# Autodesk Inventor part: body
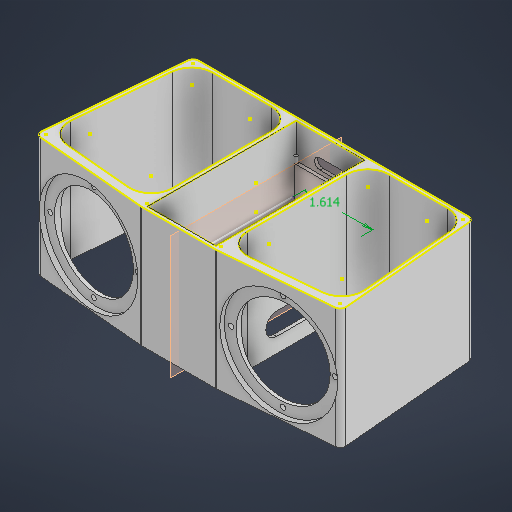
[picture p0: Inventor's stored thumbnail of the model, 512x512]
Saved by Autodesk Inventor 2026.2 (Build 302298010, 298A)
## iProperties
Created: 2026-08
Part Number: body
Material: Generic
Document SubType Name: Modeling
Designer: cpEwe
Density: 1 g/cm^3
Appearance: Default
Author: cpEwe
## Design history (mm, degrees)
sketch "Sketch1"
  geometry: L1 (-17.25, 41.25)-(17.25, 41.25); L2 (17.25, 41.25)-(17.25, -41.25); L3 (17.25, -41.25)-(-17.25, -41.25); L4 (-17.25, -41.25)-(-17.25, 41.25); L5 (-17.25, 41.25)-(17.25, -41.25); L6 (17.25, 41.25)-(-17.25, -41.25); C1 r 1 at (17.25, 41.25); C2 r 1 at (17.25, -41.25); C3 r 1 at (-17.25, -41.25); C4 r 1 at (-17.25, 41.25); 1 further point
  constraints: 12 end point, 4 centre point, 4 coincident, 3 equal radius, 2 midpoint, 2 parallel, 1 horizontal, 1 perpendicular
  dimensions: "d0" = 82.5 distance of L1.end L2.end; "d1" = 34.5 distance of L2.end L3.end; "d2" = 2 diameter of C1
extrude "Extrusion1" new body sketch "Sketch1" distance "d3" = 25; taper "d4" = 0 deg
sketch "Sketch2"
  geometry: L1 (0, 0)-(34.5, 0); L2 (34.5, 0)-(34.5, -82.5); L3 (34.5, -82.5)-(0, -82.5); L4 (36, -47.65)-(36, -82.65); L5 (36, -82.65)-(-1.5, -82.65); L6 (-1.5, -82.65)-(-1.5, -47.65); L7 (-1.5, -47.65)-(36, -47.65); L8 (36, -47.65)-(-1.5, -82.65); L9 (36, -82.65)-(-1.5, -47.65); L10 (0, -82.5)-(0, 0); C1 r 1 at (0, 0) reference; C2 r 1 at (34.5, -82.5) reference; C3 r 1 at (-1.5, -82.65); C4 r 1 at (-1.5, -47.65); C5 r 1 at (36, -47.65); C6 r 1 at (36, -82.65); 2 further points
  constraints: 20 end point, 4 centre point, 4 coincident, 3 equal radius, 3 parallel, 3 perpendicular, 2 midpoint, 1 horizontal
  dimensions: "d5" = 35 distance of L5.end L6.end; "d6" = 37.5 distance of L6.end L4.start; "d7" = 2 diameter of C3
extrude "Extrusion2" join sketch "Sketch2" distance "d8" = 7; taper "d9" = 0 deg
sketch "Sketch5"
  geometry: L1 (-3.25, 85.75)-(37.75, 85.75); L2 (37.75, 85.75)-(37.75, -3.25); L3 (37.75, -3.25)-(-3.25, -3.25); L4 (-3.25, -3.25)-(-3.25, 85.75); L5 (-3.25, 85.75)-(37.75, -3.25); L6 (37.75, 85.75)-(-3.25, -3.25); L7 (39.655, 87.655)-(-5.155, 87.655); L8 (-5.155, 87.655)-(-5.155, -5.155); L9 (-5.155, -5.155)-(39.655, -5.155); L10 (39.655, -5.155)-(39.655, 87.655); 1 further point
  constraints: 20 end point, 4 parallel, 2 midpoint, 2 perpendicular, 1 horizontal, 3 other
  dimensions: "d14" = 41 distance of L2.end L3.end; "d27" = 89 distance of L3.end L1.start; "d28" = 1.905 distance between parallel lines of L1 L7
extrude "Extrusion4" join sketch "Sketch5" stored distance "d16" = 2.54; taper "d17" = 0 deg
sketch "Sketch6"
  geometry: L1 (34.5, 0)-(0, 0); L2 (34.5, -1)-(0, -1); L3 (0, 1)-(34.5, 1); L4 (0, 82.5)-(34.5, 82.5); L5 (0, 83.5)-(34.5, 83.5); L6 (34.5, 81.5)-(0, 81.5); A1 r 1 centre (34.5, 0) between (34.5, -1) and (34.5, 1) reference; A2 r 1 centre (0, 0) between (0, -1) and (0, 1) reference; A3 r 1 centre (34.5, 0) between (34.5, -1) and (34.5, 1); A4 r 1 centre (0, 0) between (0, 1) and (0, -1); A5 r 1 centre (0, 82.5) between (0, 83.5) and (0, 81.5) reference; A6 r 1 centre (34.5, 82.5) between (34.5, 83.5) and (34.5, 81.5) reference; A7 r 1 centre (0, 82.5) between (0, 83.5) and (0, 81.5); A8 r 1 centre (34.5, 82.5) between (34.5, 81.5) and (34.5, 83.5); 3 further points
  constraints: 16 end point, 8 point on circle, 8 tangent, 4 centre point, 2 horizontal, 2 midpoint, 2 parallel
extrude "Extrusion5" join sketch "Sketch6" distance "d18" = 20; taper "d19" = 0 deg
sketch "Sketch7"
  geometry: L1 (36, -82.65)-(36, -47.65); L2 (35, -82.65)-(35, -47.65); L3 (37, -47.65)-(37, -82.65); L4 (-1.5, -82.65)-(-1.5, -47.65); L5 (-0.5, -82.65)-(-0.5, -47.65); L6 (-2.5, -47.65)-(-2.5, -82.65); A1 r 1 centre (36, -82.65) between (35, -82.65) and (37, -82.65) reference; A2 r 1 centre (36, -47.65) between (35, -47.65) and (37, -47.65) reference; A3 r 1 centre (36, -82.65) between (35, -82.65) and (37, -82.65); A4 r 1 centre (36, -47.65) between (37, -47.65) and (35, -47.65); A5 r 1 centre (-1.5, -82.65) between (-0.5, -82.65) and (-2.5, -82.65) reference; A6 r 1 centre (-1.5, -47.65) between (-0.5, -47.65) and (-2.5, -47.65) reference; A7 r 1 centre (-1.5, -82.65) between (-2.5, -82.65) and (-0.5, -82.65); A8 r 1 centre (-1.5, -47.65) between (-0.5, -47.65) and (-2.5, -47.65); 3 further points
  constraints: 16 end point, 8 point on circle, 8 tangent, 4 centre point, 2 midpoint, 2 parallel, 2 vertical
extrude "Extrusion6" join sketch "Sketch7" distance "d20" = 3; taper "d21" = 0 deg
sketch "Sketch8"
  geometry: L1 (34.499, 83.5)-(38.654, 87.655); L2 (0.001, 83.5)-(-4.154, 87.655); L3 (0, 83.5)-(34.5, 83.5) reference; L4 (39.655, 87.655)-(-5.155, 87.655) reference; A1 r 1 centre (0, 82.5) between (0, 83.5) and (0, 81.5) reference; A2 r 1 centre (34.5, 82.5) between (34.5, 81.5) and (34.5, 83.5) reference; A3 r 1 centre (0, 82.5) between (0, 83.5) and (0, 81.5) reference; 6 further points
  constraints: 4 end point, 2 point on circle, 2 point on line
extrude "Extrusion7" cut sketch "Sketch8" distance "d24" = 3; taper "d25" = 0 deg
sketch "Sketch9"
  geometry: L1 (37.75, -1.129)-(-3.25, -1.129); L2 (-3.25, -1.129)-(-3.25, 83.629); L3 (-3.25, 83.629)-(37.75, 83.629); L4 (37.75, 83.629)-(37.75, -1.129); L5 (37.75, -1.129)-(-3.25, 83.629); L6 (-3.25, -1.129)-(37.75, 83.629); 1 further point
  constraints: 12 end point, 2 midpoint, 2 parallel, 1 horizontal, 1 perpendicular
  dimensions: "d26" = 41 distance of L2.end L3.end
sketch "Sketch10"
  geometry: L1 (-5.155, 87.655)-(-5.155, -5.155) reference; L2 (-5.155, -5.155)-(39.655, -5.155) reference; L3 (39.655, -5.155)-(39.655, 87.655) reference; L4 (39.655, 87.655)-(-5.155, 87.655) reference; L5 (0, 83.5)-(34.5, 83.5) reference; L6 (34.5, 81.5)-(0, 81.5) reference; L7 (34.5, -1)-(0, -1) reference; L8 (0, 1)-(34.5, 1) reference; L9 (-3.25, -3.25)-(-3.25, 85.75); L10 (-3.25, 85.75)-(37.75, 85.75); L11 (37.75, 85.75)-(37.75, -3.25); L12 (37.75, -3.25)-(-3.25, -3.25); A1 r 1 centre (34.5, 82.5) between (34.5, 81.5) and (34.5, 83.5) reference; A2 r 1 centre (0, 82.5) between (0, 83.5) and (0, 81.5) reference; A3 r 1 centre (0, 0) between (0, 1) and (0, -1) reference; A4 r 1 centre (34.5, 0) between (34.5, -1) and (34.5, 1) reference; 1 further point
  constraints: 8 end point, 3 other
  dimensions: "d29" = 1.905 distance between parallel lines of L1 L9
extrude "Extrusion8" join sketch "Sketch10" stored distance "d30" = 67; taper "d31" = 0 deg
sketch "Sketch11"
  geometry: L1 (5.155, -13.5)-(39.655, -13.5) reference; L2 (16.055, -10.325)-(28.755, -10.325); L3 (6.155, -9.77)-(4.155, -9.77) reference; L4 (16.055, -13.5)-(28.755, -13.5); L5 (28.755, -7.15)-(16.055, -7.15); L6 (4.655, -39.04)-(22.405, -39.04); L7 (22.405, -39.04)-(22.405, -67); L8 (1.905, -67)-(42.905, -67) reference; L9 (15.905, -39.04)-(27.905, -39.04); L10 (27.905, -39.04)-(27.905, -53.04); L11 (27.905, -53.04)-(15.905, -53.04); L12 (15.905, -53.04)-(15.905, -39.04); A1 r 3.175 centre (16.055, -10.325) between (16.055, -7.15) and (16.055, -13.5); A2 r 3.175 centre (28.755, -10.325) between (28.755, -13.5) and (28.755, -7.15); 6 further points
  constraints: 20 end point, 4 parallel, 4 point on circle, 4 tangent, 2 centre point, 2 horizontal, 2 midpoint, 1 collinear, 1 perpendicular, 1 point on line
  dimensions: "d32" = 12.7 distance of L5.start L5.end; "d33" = 3.175 radius of A2; "d41" = 12 distance of L10.end L11.end; "d42" = 14 distance of L11.end L9.start; "d43" = 6.5 distance between parallel lines of L12 L7
extrude "Extrusion9" cut sketch "Sketch11" distance "d34" = 67; taper "d35" = 0 deg
chamfer "Chamfer1" distance "d44" = 1.905; stored, may be unused: second distance "d45" = 3.175, angle "d46" = 45 deg
fillet "Fillet2" dims "d47" = 3.175
sketch "Sketch12"
  geometry: L1 (39.655, 5.155)-(111.894, -1.165); L2 (39.655, 1.968)-(106.4, -3.872); L3 (39.655, 1.968)-(106.4, -3.872); L4 (106.4, -3.872)-(99.237, -85.75); L5 (98.165, -97.995)-(31.42, -92.155); L6 (31.42, -92.155)-(39.655, 1.968); L7 (108.575, -0.875)-(100.982, -87.655); L8 (-5.155, -87.655)-(39.655, -87.655) reference; L9 (39.655, -94.788)-(29.357, -93.887); L10 (-5.155, -87.655)-(31.814, -87.655); L11 (39.655, -87.655)-(100.982, -87.655); L12 (39.655, -85.75)-(99.237, -85.75); L13 (39.655, -87.655)-(39.655, 5.155) reference; L14 (39.655, -87.655)-(39.655, 5.155); L15 (39.655, 5.155)-(37.668, 5.155); L16 (37.668, 5.155)-(37.668, -87.655); L17 (37.668, -87.655)-(39.655, -87.655); L18 (106.236, -5.752)-(39.655, 0.161); 3 further points
  constraints: 32 end point, 6 parallel, 4 collinear, 4 point on line, 2 perpendicular
  dimensions: "d53" = 3.175 distance between parallel lines of L1 L2; "d54" = 5.49357 horizontal distance of L2.end L1.end; "d55" = 1.905 distance between parallel lines of L4 L7; "d56" = 1.905 distance between parallel lines of L11 L12; "d62" = 0.075 deg angle of L2 L18
extrude "Extrusion10" join sketch "Sketch12" distance "d57" = 67; taper "d58" = 0 deg
workplane "Work Plane1"
sketch "Sketch14"
  geometry: L1 (0, 0)-(-69.183, 0) reference; L2 (-69.183, 0)-(0, 66.639); C1 r 32.5 at (-34.591, 33.319); 1 further point
  constraints: 2 end point, 1 centre point, 1 midpoint
  dimensions: "d63" = 65 diameter of C1
extrude "Extrusion12" cut sketch "Sketch14" distance "d64" = 3; taper "d65" = 0 deg
sketch "Sketch15"
  geometry: C1 r 26 at (0, 0); 1 further point
  constraints: 1 centre point
  dimensions: "d66" = 52 diameter of C1
extrude "Extrusion13" cut sketch "Sketch15" distance "d67" = 3; taper "d68" = 0 deg
sketch "Sketch16"
  geometry: L1 (0, 0)-(0, 30.96) reference; L2 (89, 0)-(0, 0) reference; L3 (89, 30.96)-(89, 0) reference; L4 (0, 30.96)-(89, 30.96) reference; L5 (8.89, 8.89)-(8.89, 22.07); L6 (8.89, 22.07)-(80.11, 22.07); L7 (80.11, 22.07)-(80.11, 8.89); L8 (80.11, 8.89)-(8.89, 8.89); L9 (44.5, 8.89)-(44.5, 22.07); L10 (60.982, 8.89)-(28.018, 8.89); L11 (28.018, 8.89)-(28.018, 22.07); L12 (28.018, 22.07)-(60.982, 22.07); L13 (60.982, 22.07)-(60.982, 8.89); L14 (60.982, 8.89)-(28.018, 22.07); L15 (28.018, 8.89)-(60.982, 22.07); 5 further points
  constraints: 22 end point, 5 midpoint, 2 parallel, 1 horizontal, 1 perpendicular, 1 point on line, 3 other
  dimensions: "d69" = 8.89 distance between parallel lines of L2 L8
extrude "Extrusion14" cut sketch "Sketch16" stored distance "d70" = 15.69999; taper "d71" = 0 deg
mirror "Mirror2"
fillet "Fillet3" dims "d72" = 6.35
fillet "Fillet4" dims "d73" = 12.7
fillet "Fillet5" dims "d74" = 3.175
sketch "Sketch17"
  geometry: 1 further point
sketch "Sketch18"
  geometry: L1 (39.516, -5.155)-(-5.098, -5.155) reference; L2 (39.793, -5.143)-(105.412, 0.598) reference; L3 (108.298, 4.038)-(101.236, 84.757) reference; L4 (98.073, 87.655)-(-63.655, 87.655) reference; L5 (-73.88, 4.038)-(-66.818, 84.757) reference; L6 (-5.375, -5.143)-(-70.993, 0.598) reference; L7 (-65.833, 74.157)-(-70.712, 18.387) reference; L8 (-17.937, 85.75)-(-53.181, 85.75) reference; L9 (-5.237, 13.717)-(-5.237, 73.05) reference; L10 (-59.184, 4.63)-(-19.06, 1.066) reference; L11 (-3.25, 85.75)-(37.668, 85.75) reference; L12 (37.668, 85.75)-(37.668, -3.25) reference; L13 (37.668, -3.25)-(-3.25, -3.25) reference; L14 (-3.25, -3.25)-(-3.25, 85.75) reference; L15 (52.355, 85.75)-(87.599, 85.75) reference; L16 (100.251, 74.157)-(105.13, 18.387) reference; L17 (93.602, 4.63)-(53.478, 1.066) reference; L18 (39.655, 13.717)-(39.655, 73.05) reference; A1 r 3.175 centre (-5.098, -1.98) between (-5.375, -5.143) and (-5.098, -5.155) reference; A2 r 3.175 centre (39.516, -1.98) between (39.516, -5.155) and (39.793, -5.143) reference; A3 r 3.175 centre (105.135, 3.761) between (105.412, 0.598) and (108.298, 4.038) reference; A4 r 3.175 centre (98.073, 84.48) between (101.236, 84.757) and (98.073, 87.655) reference; A5 r 3.175 centre (-63.655, 84.48) between (-63.655, 87.655) and (-66.818, 84.757) reference; A6 r 3.175 centre (-70.717, 3.761) between (-73.88, 4.038) and (-70.993, 0.598) reference; A7 r 12.7 centre (-58.06, 17.28) between (-70.712, 18.387) and (-59.184, 4.63) reference; A8 r 12.7 centre (-53.181, 73.05) between (-53.181, 85.75) and (-65.833, 74.157) reference; A9 r 12.7 centre (-17.937, 73.05) between (-5.237, 73.05) and (-17.937, 85.75) reference; A10 r 12.7 centre (-17.937, 13.717) between (-19.06, 1.066) and (-5.237, 13.717) reference; A11 r 12.7 centre (87.599, 73.05) between (100.251, 74.157) and (87.599, 85.75) reference; A12 r 12.7 centre (92.478, 17.28) between (93.602, 4.63) and (105.13, 18.387) reference; A13 r 12.7 centre (52.355, 13.717) between (39.655, 13.717) and (53.478, 1.066) reference; A14 r 12.7 centre (52.355, 73.05) between (52.355, 85.75) and (39.655, 73.05) reference; 1 further point
extrude "Extrusion15" join sketch "Sketch18" distance "d75" = 5; taper "d76" = 0 deg
sketch "Sketch19"
  geometry: L1 (-70.993, 0.598)-(-5.375, -5.143) reference; L2 (-5.098, -5.155)-(39.516, -5.155) reference; L3 (39.793, -5.143)-(105.412, 0.598) reference; L4 (108.298, 4.038)-(101.236, 84.757) reference; L5 (98.073, 87.655)-(-63.655, 87.655) reference; L6 (-66.818, 84.757)-(-73.88, 4.038) reference; L7 (39.655, 13.717)-(39.655, 73.05) reference; L8 (52.355, 85.75)-(87.599, 85.75) reference; L9 (100.251, 74.157)-(105.13, 18.387) reference; L10 (93.602, 4.63)-(53.478, 1.066) reference; L11 (-3.25, 85.75)-(37.668, 85.75) reference; L12 (37.668, 85.75)-(37.668, -3.25) reference; L13 (37.668, -3.25)-(-3.25, -3.25) reference; L14 (-3.25, -3.25)-(-3.25, 85.75) reference; L15 (-70.712, 18.387)-(-65.833, 74.157) reference; L16 (-53.181, 85.75)-(-17.937, 85.75) reference; L17 (-5.237, 73.05)-(-5.237, 13.717) reference; L18 (-19.06, 1.066)-(-59.184, 4.63) reference; A1 r 3.175 centre (-5.098, -1.98) between (-5.375, -5.143) and (-5.098, -5.155) reference; A2 r 3.175 centre (39.516, -1.98) between (39.516, -5.155) and (39.793, -5.143) reference; A3 r 3.175 centre (105.135, 3.761) between (105.412, 0.598) and (108.298, 4.038) reference; A4 r 3.175 centre (98.073, 84.48) between (101.236, 84.757) and (98.073, 87.655) reference; A5 r 3.175 centre (-63.655, 84.48) between (-63.655, 87.655) and (-66.818, 84.757) reference; A6 r 3.175 centre (-70.717, 3.761) between (-73.88, 4.038) and (-70.993, 0.598) reference; A7 r 12.7 centre (52.355, 73.05) between (52.355, 85.75) and (39.655, 73.05) reference; A8 r 12.7 centre (87.599, 73.05) between (100.251, 74.157) and (87.599, 85.75) reference; A9 r 12.7 centre (92.478, 17.28) between (93.602, 4.63) and (105.13, 18.387) reference; A10 r 12.7 centre (52.355, 13.717) between (39.655, 13.717) and (53.478, 1.066) reference; A11 r 12.7 centre (-53.181, 73.05) between (-53.181, 85.75) and (-65.833, 74.157) reference; A12 r 12.7 centre (-17.937, 73.05) between (-5.237, 73.05) and (-17.937, 85.75) reference; A13 r 12.7 centre (-17.937, 13.717) between (-19.06, 1.066) and (-5.237, 13.717) reference; A14 r 12.7 centre (-58.06, 17.28) between (-70.712, 18.387) and (-59.184, 4.63) reference; 1 further point
  node "Projected Loop5"
sketch "Sketch20"
  geometry: L1 (-77.167, 0.181)-(-36.405, 0.181) reference; C1 r 1.5 at (0, -28.819); C2 r 26 at (0, 0) reference; C3 r 1.5 at (28.819, 0); C4 r 1.5 at (0, 28.819); C5 r 1.5 at (-28.819, 0); 1 further point
  constraints: 4 centre point, 9 other
  dimensions: "d77" = 3 diameter of C1; "d78" = 29 distance from line of L1 C1.centre; "d81" = 360 deg dimension on C2.centre C1.centre (derived)
extrude "Extrusion16" cut sketch "Sketch20" distance "d83" = 25.4; taper "d84" = 0 deg
mirror "Mirror3"
body "Solid1"
node "Projected Loop2"
node "Projected Loop3"
node "Projected Loop4"
node "Sketch Circular Pattern1" dims "d81" = 360 deg (derived)
